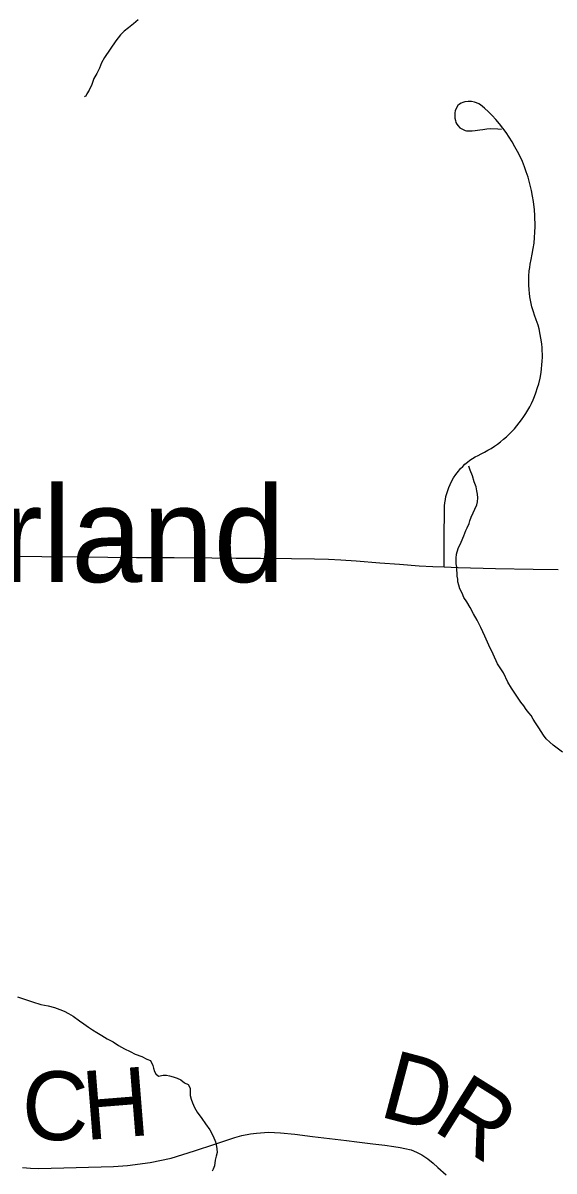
# Model space of a CAD drawing. Extents: x 103424 to 286016, y 38711 to 110967.
# Drawn here: x 110509 to 112838, y 76283 to 81319 of the extents above; entities that cross this region are included whole.
import ezdxf

# ---------------------------------------------------------------- set-up
doc = ezdxf.new("R2010")
doc.units = 0
for name, color, linetype in [('GM_X_Minor_River', 7, 'Continuous'), ('GM_X_Township_Road', 7, 'Continuous'), ('GM_X_Township_Road_Text', 7, 'Continuous'), ('GM_X_Unincorporated_Text', 7, 'Continuous'), ('GM_X_US_Route', 7, 'Continuous')]:
    doc.layers.add(name, color=color, linetype=linetype)

msp = doc.modelspace()

# ---------------------------------------------------------------- linework, layer by layer
at = {"layer": 'GM_X_Minor_River'}
for points in [[(111013.6, 81332.3), (110993.5, 81315.9), (110971.5, 81297.5), (110953.5, 81283.2), (110937.6, 81266.8), (110915.7, 81240.4), (110866, 81167.1), (110854.2, 81144.8), (110844.4, 81120.5), (110832.5, 81098.1), (110820.6, 81075.8), (110810.8, 81049.4), (110799, 81025.1), (110789.1, 81008.8), (110785.2, 80998.7), (110781.2, 80996.6), (110779.2, 80994.6)], [(112408.3, 78970.7), (112410.1, 78988.9), (112417.9, 79013.2), (112429.7, 79041.6), (112441.5, 79070), (112451.3, 79092.3), (112457.2, 79104.5), (112465.1, 79122.7), (112469, 79134.9), (112474.9, 79151.1), (112498.5, 79205.9), (112502.4, 79218.1), (112504.2, 79236.2), (112502, 79252.4), (112499.8, 79266.5), (112495.5, 79284.6), (112487.2, 79306.8), (112480.8, 79333), (112470.5, 79357.1), (112464.7, 79375.2)], [(112874.6, 78120.9), (112833.9, 78150.8), (112819.6, 78164.8), (112803.2, 78178.7), (112790.9, 78194.8), (112780.7, 78210.8), (112770.4, 78226.9), (112756, 78249), (112745.7, 78265), (112737.4, 78281.1), (112727.2, 78293.1), (112714.9, 78307.1), (112704.6, 78323.2), (112692.3, 78339.2), (112680, 78357.3), (112665.6, 78379.4), (112651.2, 78401.4), (112634.7, 78427.5), (112616.1, 78467.7), (112589.4, 78507.9), (112570.7, 78550.1), (112552.1, 78590.3), (112533.5, 78628.5), (112516.9, 78666.7), (112500.3, 78698.9), (112483.8, 78727), (112469.4, 78755.1), (112455, 78779.2), (112442.6, 78799.3), (112434.3, 78817.4), (112424, 78837.5), (112419.8, 78853.6), (112415.6, 78867.7), (112415.4, 78879.8), (112413.3, 78891.9), (112413.1, 78906.1), (112410.9, 78918.2), (112410.8, 78932.3), (112408.6, 78946.4), (112408.5, 78956.5), (112408.3, 78970.7)], [(110485.8, 77046.6), (110516.2, 77036.8), (110550.6, 77025), (110587.1, 77013.3), (110619.5, 77007.5), (110647.9, 76999.7), (110670.2, 76991.9), (110690.5, 76984), (110708.8, 76974.1), (110729.1, 76962.2), (110757.6, 76942.2), (110775.9, 76928.3), (110796.3, 76914.4), (110814.6, 76902.4), (110832.9, 76890.5), (110855.3, 76876.6), (110877.7, 76862.7), (110904.1, 76848.8), (110928.5, 76832.9), (110954.9, 76819), (110979.3, 76807.1), (111001.7, 76795.2), (111030.1, 76785.4), (111052.4, 76773.5), (111068.6, 76767.6), (111079, 76745.5), (111081.1, 76733.4), (111085.4, 76719.3), (111091.5, 76709.2), (111103.8, 76699.3), (111123.9, 76703.5), (111138.1, 76703.7), (111152.2, 76699.8), (111168.4, 76695.9), (111184.7, 76690), (111200.9, 76682.1), (111217.2, 76670.1), (111233.5, 76662.2), (111241.7, 76646.1), (111241.9, 76627.9), (111242.1, 76613.8), (111246.3, 76597.7), (111252.6, 76581.6), (111260.9, 76561.5), (111273.2, 76541.4), (111293.8, 76513.3), (111310.2, 76489.2), (111328.7, 76463.2), (111343.1, 76435), (111353.5, 76410.9), (111357.8, 76390.7), (111359.9, 76380.7), (111360.1, 76364.5), (111356.3, 76348.3), (111352.4, 76330.1), (111348.7, 76305.8), (111342.8, 76291.6), (111338.9, 76281.5)]]:
    msp.add_lwpolyline(points, dxfattribs=at)
at = {"layer": 'GM_X_Township_Road'}
for points in [[(112355.7, 78932.8), (112356.6, 79059.7), (112357.5, 79186.7), (112358, 79200.6), (112359.3, 79214.4), (112361.3, 79228.2), (112363.8, 79241.9), (112367.1, 79255.4), (112371.4, 79268.7), (112375.9, 79281.8), (112381.5, 79294.6), (112387.5, 79307.1), (112396.6, 79323.3), (112406.9, 79338.8), (112418.3, 79353.5), (112427.3, 79364), (112437.2, 79374), (112447.2, 79383.5), (112457.8, 79392.4), (112468.9, 79400.8), (112480.5, 79408.6), (112492.5, 79415.8), (112504.6, 79422.3), (112518, 79428.7), (112532.8, 79436.3), (112547.4, 79444.5), (112561.8, 79453.1), (112575.9, 79462.3), (112589.5, 79472), (112602.8, 79482.1), (112615.9, 79492.7), (112628.5, 79503.7), (112640.6, 79515.1), (112652.4, 79527), (112664, 79539.4), (112674.8, 79552), (112685.4, 79565.1), (112695.5, 79578.5), (112705.1, 79592.2), (112714.2, 79606.3), (112722.7, 79620.7), (112730.8, 79635.4), (112738.3, 79650.3), (112745.4, 79665.6), (112751.9, 79681), (112757.7, 79696.6), (112765.8, 79720.5), (112770.4, 79736.6), (112776.2, 79761.1), (112780.7, 79785.8), (112783, 79802.4), (112784.7, 79819.1), (112785.7, 79835.8), (112786.3, 79852.6), (112785, 79894.4), (112783.5, 79911.1), (112780.3, 79936), (112777.3, 79952.5), (112771.7, 79977), (112767.4, 79993.2), (112759.7, 80017.2), (112752.1, 80037.7), (112747.3, 80052), (112740.8, 80073.9), (112737.3, 80088.5), (112731.5, 80118.3), (112729.5, 80133.3), (112728, 80148.4), (112726.5, 80171), (112727, 80208.9), (112728.8, 80231.6), (112730.8, 80246.6), (112733.1, 80261.5), (112737.1, 80281.6), (112742.2, 80305.5), (112746.5, 80329.4), (112749.8, 80353.6), (112752.3, 80377.8), (112753.8, 80402.1), (112754.5, 80426.4), (112753.6, 80475.1), (112751.8, 80499.4), (112747.5, 80535.7), (112743.8, 80559.7), (112739, 80583.6), (112730.5, 80619), (112723.7, 80642.5), (112716.1, 80665.6), (112707.6, 80688.5), (112698.6, 80711), (112688.5, 80733.2), (112677.7, 80755.1), (112666.4, 80776.5), (112654, 80797.6), (112640.9, 80818.2), (112627.4, 80838.3), (112613, 80858), (112597.9, 80877.1), (112582.3, 80895.8), (112566, 80913.8), (112549.6, 80929.6), (112532.7, 80945.8), (112524.6, 80953.1), (112514.7, 80960.5), (112507.9, 80964.1), (112498.1, 80968.9), (112488.2, 80971.9), (112475.3, 80974.1), (112461, 80974.8), (112446.3, 80973), (112437.3, 80970.5), (112429.8, 80967.5), (112423.3, 80963.6), (112416.5, 80957.2), (112407.3, 80941.7), (112404.4, 80933.3), (112402.9, 80924.8), (112402.2, 80917.4), (112402.8, 80901.6), (112405.1, 80891.3), (112407.6, 80882.7), (112411, 80874.8), (112416.9, 80867.5), (112424.6, 80859.7), (112435.6, 80853.1), (112447.8, 80848), (112454.4, 80846.7), (112461.7, 80845.4), (112479, 80846.1), (112491.5, 80847.9), (112511.7, 80850.5), (112525.3, 80852.3), (112543.4, 80854.6), (112558.1, 80855.7), (112590.5, 80854.5), (112607.3, 80853.5)], [(110507.2, 76297.6), (110542.2, 76294.8), (110578.8, 76294.1), (110742.6, 76298.2), (110906.5, 76302.3), (110967.7, 76306.5), (111066.6, 76320.1), (111158.9, 76339.8), (111261.7, 76371.8), (111350, 76400.6), (111438.3, 76429.5), (111468.6, 76438.8), (111507.3, 76446.3), (111533.7, 76448.4), (111585.4, 76452.6), (111638.7, 76450.7), (111701.4, 76445.1), (111779.2, 76434.1), (111852.7, 76425.3), (111928, 76416.3), (111973.4, 76410.8), (112043.5, 76402.4), (112096.4, 76396), (112135.6, 76390.8), (112163.5, 76386.6), (112182.9, 76382.2), (112210.6, 76375), (112234.9, 76365.9), (112258.4, 76353.8), (112283.8, 76336.5), (112307.1, 76317.2), (112327.8, 76298.7), (112364, 76265.7)]]:
    msp.add_lwpolyline(points, dxfattribs=at)
at = {"layer": 'GM_X_US_Route'}
msp.add_lwpolyline([(110428.2, 78979.7), (110591.5, 78979.2), (110756.5, 78977.4), (110881.6, 78976.1), (111006.6, 78974.7), (111171.7, 78973.7), (111336.7, 78972.6), (111443.7, 78971.9), (111550.7, 78971.2), (111686.9, 78970), (111787.3, 78968.4), (111848.3, 78966.6), (111902.6, 78964.5), (111969.7, 78959.5), (112073.2, 78951.3), (112159.6, 78944.8), (112245.9, 78938.3), (112305.8, 78934.8), (112355.7, 78932.8), (112416.6, 78929.7), (112581.6, 78926.4), (112746.7, 78923), (112855.1, 78920.9)], dxfattribs=at)
msp.add_lwpolyline([(110428.2, 78979.7), (110591.5, 78979.2), (110756.5, 78977.4), (110881.6, 78976.1), (111006.6, 78974.7), (111171.7, 78973.7), (111336.7, 78972.6), (111443.7, 78971.9), (111550.7, 78971.2), (111686.9, 78970), (111787.3, 78968.4), (111848.3, 78966.6), (111902.6, 78964.5), (111969.7, 78959.5), (112073.2, 78951.3), (112159.6, 78944.8), (112245.9, 78938.3), (112305.8, 78934.8), (112355.7, 78932.8), (112416.6, 78929.7), (112581.6, 78926.4), (112746.7, 78923), (112855.1, 78920.9)], dxfattribs=at)

# ---------------------------------------------------------------- texts
at = {"layer": 'GM_X_Township_Road_Text'}
for s, rotation, p in [('D', 345.1615, (112063.8, 76524.1)), ('C', 359.1962, (110503.1, 76420.5)), ('H', 4.5622, (110781.9, 76418)), ('R', 327.8916, (112298.6, 76465.7))]:
    msp.add_text(s, height=301.9, rotation=rotation, dxfattribs=at).set_placement(p)
at = {"layer": 'GM_X_Unincorporated_Text'}
msp.add_text('Chesterland', height=419.602, rotation=0, dxfattribs=at).set_placement((108631.7, 78866.5))

doc.saveas('drawing.dxf')
